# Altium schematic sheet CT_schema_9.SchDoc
size 254 x 194 mm
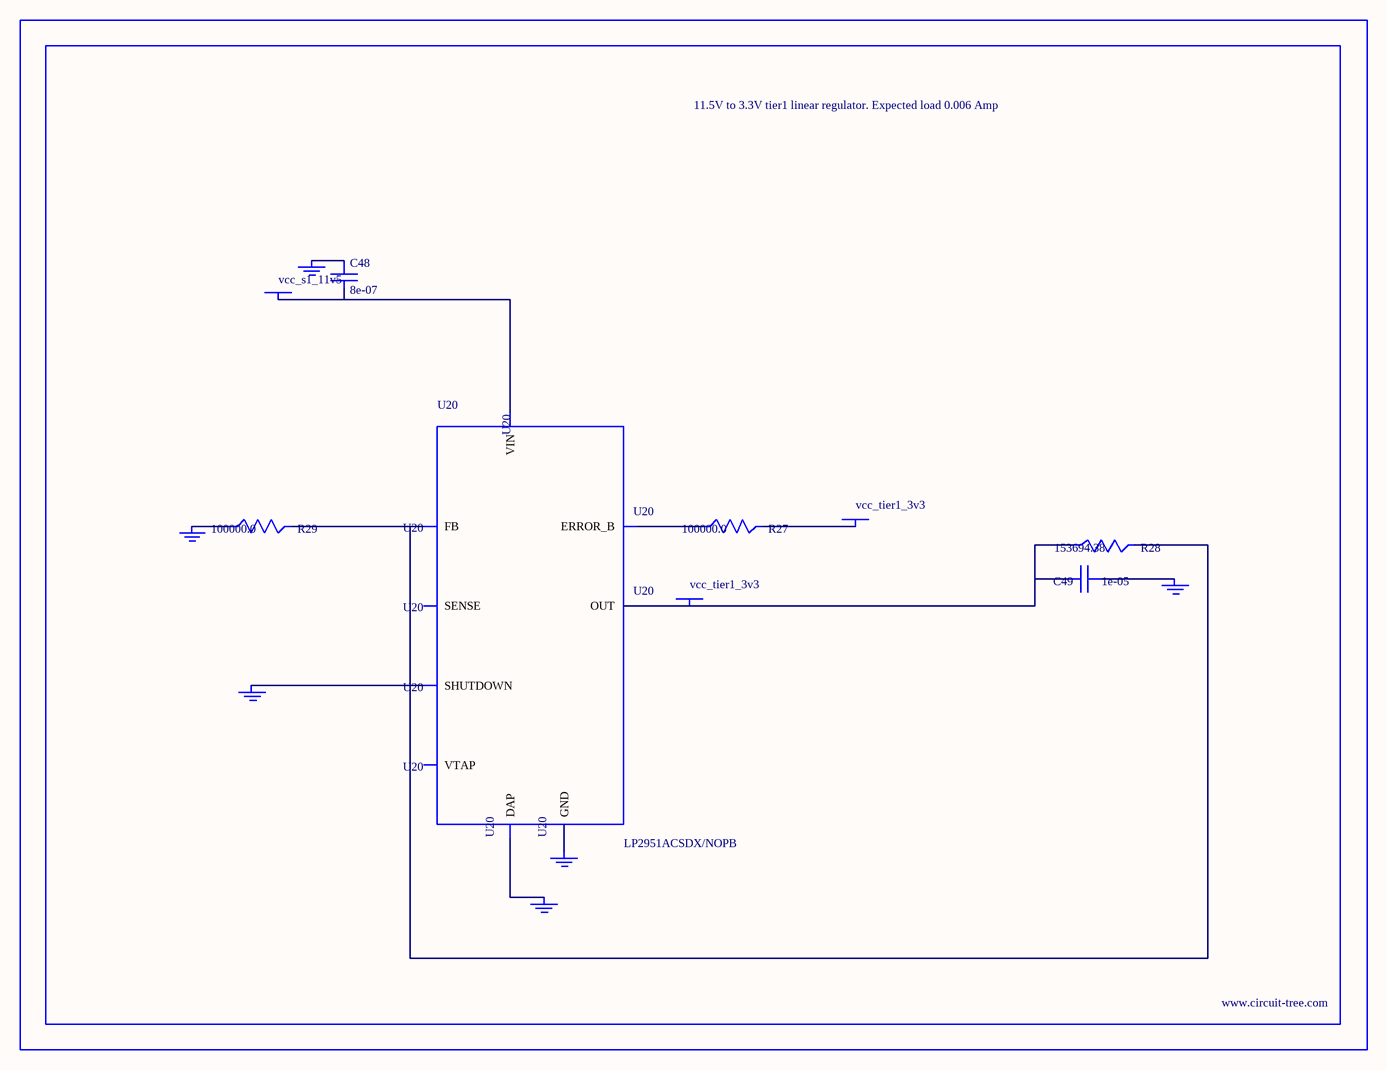
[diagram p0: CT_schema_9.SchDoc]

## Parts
BORDER8  (no value)
C48  8e-07  [R0603]
C49  1e-05  [C1210]
GND_INSTANCE_8_0  (no value)
GND_INSTANCE_8_1  (no value)
GND_INSTANCE_8_2  (no value)
GND_INSTANCE_8_3  (no value)
GND_INSTANCE_8_4  (no value)
GND_INSTANCE_8_5  (no value)
POWER_INSTANCE_8_0  vcc_tier1_3v3
POWER_INSTANCE_8_1  vcc_s1_11v5
POWER_INSTANCE_8_2  vcc_tier1_3v3
R27  100000.0  [R0603]
R28  153694.38  [R0603]
R29  100000.0  [R0603]
U20  LP2951ACSDX/NOPB  [WSON-8]

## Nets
NetC48_1: C48.1 GND_INSTANCE_8_3.0(GND)
NetC48_2: C48.2 POWER_INSTANCE_8_1.0(PWR) U20.8(VIN)
NetC49_1: C49.1 GND_INSTANCE_8_0.0(GND)
NetC49_2: C49.2 POWER_INSTANCE_8_2.0(PWR) R28.1 U20.1(OUT)
NetGND_INSTANCE_8_1_0: GND_INSTANCE_8_1.0(GND) U20.3(SHUTDOWN)
NetGND_INSTANCE_8_2_0: GND_INSTANCE_8_2.0(GND) R29.1
NetGND_INSTANCE_8_4_0: GND_INSTANCE_8_4.0(GND) U20.PAD(DAP)
NetGND_INSTANCE_8_5_0: GND_INSTANCE_8_5.0(GND) U20.4(GND)
NetPOWER_INSTANCE_8_0_0: POWER_INSTANCE_8_0.0(PWR) R27.2
NetR27_1: R27.1 U20.5(ERROR_B)
NetR28_2: R28.2 R29.2 U20.7(FB)

Not connected (* = marked no-connect by the designer): U20 2(SENSE) 6(VTAP)

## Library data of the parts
BORDER8 = BORDER_PAGE8
C48 = C48
C49 = GRM32DR61E106MA12L
GND_INSTANCE_8_0-GND_INSTANCE_8_5 = GND
POWER_INSTANCE_8_0-POWER_INSTANCE_8_2 = PWR
R27 R29 = RC0603JR-07100KL
R28 = R28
